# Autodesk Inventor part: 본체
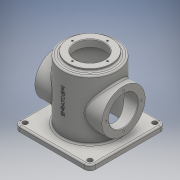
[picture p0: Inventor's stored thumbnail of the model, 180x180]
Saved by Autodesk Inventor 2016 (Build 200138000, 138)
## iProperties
Created: 2019-08
Part Number: 본체
Material: 일반
Document SubType Name: Modeling
Designer: user
Density: 1 g/cm^3
Appearance: 기본값
Author: user
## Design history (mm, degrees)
sketch "스케치1"
  geometry: L1 (-60, -70)-(60, -70); L2 (70, -60)-(70, 60); L3 (60, 70)-(-60, 70); L4 (-70, 60)-(-70, -60); L5 (-70, -70)-(70, 70); L6 (70, -70)-(-70, 70); A1 r 10 centre (-60, 60) between (-60, 70) and (-70, 60); A2 r 10 centre (60, 60) between (70, 60) and (60, 70); A3 r 10 centre (60, -60) between (60, -70) and (70, -60); A4 r 10 centre (-60, -60) between (-70, -60) and (-60, -70); 1 further point
  constraints: 12 end point, 8 point on circle, 8 point on line, 8 tangent, 4 centre point, 3 equal radius, 2 midpoint, 2 parallel, 1 horizontal, 1 perpendicular
  dimensions: "d0" = 140 distance of L5.end L6.end; "d1" = 140 distance of L6.start L5.end; "d2" = 10 radius of A1
extrude "돌출1" new body sketch "스케치1" distance "d3" = 10; taper "d4" = 0 deg
node "작업 평면1"
sketch "스케치8"
  geometry: C1 r 50 at (0, 0); 1 further point
  constraints: 1 centre point, 1 coincident
  dimensions: "d28" = 100 diameter of C1
extrude "돌출6" join sketch "스케치8" distance "d29" = 110; taper "d30" = 0 deg
node "작업 평면3"
sketch "스케치10"
  geometry: C1 r 40 at (0, 0); 1 further point
  constraints: 1 centre point, 1 coincident
  dimensions: "d32" = 80 diameter of C1
extrude "돌출7" join sketch "스케치10" stored distance "d33" = 110; taper "d34" = 0 deg
sketch "스케치11"
  geometry: L1 (-60, 70)-(60, 70) reference; L2 (70, 60)-(70, -60) reference; L3 (60, -70)-(-60, -70) reference; L4 (-70, -60)-(-70, 60) reference; C1 r 50 at (0, 0) reference; A1 r 10 centre (-60, 60) between (-60, 70) and (-70, 60) reference; A2 r 10 centre (60, 60) between (70, 60) and (60, 70) reference; A3 r 10 centre (60, -60) between (60, -70) and (70, -60) reference; A4 r 10 centre (-60, -60) between (-70, -60) and (-60, -70) reference; 5 further points
  constraints: 4 coincident
hole "구멍2" sketch "스케치11" at (-60, 60), (60, 60), (60, -60), (-60, -60) diameter "d35" = 9; stored, may be unused: countersink angle "d39" = 90 deg, drill point angle "d41" = 118 deg; dims "d36" = 6, "d37" = 4, "d38" = 2, "d40" = 8
node "작업 평면4"
sketch "스케치12"
  geometry: L1 (-60, 0)-(60, 0) reference; C1 r 40 at (0, 60); 2 further points
  constraints: 1 centre point, 1 midpoint, 1 vertical alignment
  dimensions: "d43" = 80 diameter of C1; "d44" = 60 distance from line of L1 C1.centre
extrude "돌출8" join sketch "스케치12" distance "d45" = 124; taper "d46" = 0 deg
sketch "스케치13"
  geometry: C1 r 45 at (0, 0); 1 further point
  constraints: 1 centre point, 1 coincident
  dimensions: "d47" = 90 diameter of C1
extrude "돌출9" cut sketch "스케치13" distance "d48" = 112; taper "d49" = 0 deg
sketch "스케치14"
  geometry: 2 further points
  constraints: 1 coincident
hole "구멍3" sketch "스케치14" at (0, 0) diameter "d50" = 54; stored, may be unused: countersink angle "d54" = 90 deg, drill point angle "d56" = 118 deg; dims "d51" = 6, "d52" = 4, "d53" = 2, "d55" = 8
sketch "스케치15"
  geometry: C1 r 40 at (0, 0) reference; 2 further points
  constraints: 1 coincident
hole "구멍4" sketch "스케치15" at (0, 0) diameter "d57" = 54; stored, may be unused: countersink angle "d61" = 90 deg, drill point angle "d63" = 118 deg; dims "d58" = 6, "d59" = 4, "d60" = 2, "d62" = 8
sketch "스케치16" dims "d64" = 65
  geometry: C1 r 27 at (0, 0) reference; 3 further points
  constraints: 2 vertical alignment, 1 coincident, 2 other
hole "구멍5" sketch "스케치16" at (0, -32.5) diameter "d65" = 3.242; stored, may be unused: countersink angle "d69" = 90 deg, drill point angle "d71" = 118 deg; dims "d66" = 8, "d67" = 4, "d68" = 2, "d70" = 10
sketch "스케치17" dims "d75" = 65
  geometry: 3 further points
  constraints: 2 vertical alignment, 1 coincident, 2 other
hole "구멍6" sketch "스케치17" at (0, 32.5) diameter "d76" = 3.242; stored, may be unused: countersink angle "d80" = 90 deg, drill point angle "d82" = 118 deg; dims "d77" = 8, "d78" = 4, "d79" = 2, "d81" = 10
chamfer "모따기1" distance "d86" = 1; stored, may be unused: second distance "d87" = 2, angle "d88" = 45 deg
fillet "모깎기1" dims "d89" = 3
fillet "모깎기2" dims "d90" = 3
fillet "모깎기3" dims "d91" = 3
fillet "모깎기4" dims "d92" = 3
fillet "모깎기5" dims "d93" = 3
chamfer "모따기2" distance "d94" = 1; stored, may be unused: second distance "d95" = 2, angle "d96" = 45 deg
node "작업 평면5"
sketch "스케치18" dims "d0" = 140, "d1" = 140, "d2" = 10
  geometry: L1 (-60, 0)-(60, 0) reference; 3 further points
  constraints: 1 midpoint, 1 vertical alignment, 1 other
  dimensions: "d98" = 70 distance from line of L1 point (0, 70)
feature "엠보싱1" sketch "스케치18" dims "d0" = 140, "d1" = 140, "d2" = 10, "d99" = 0.5, "d100" = 0
node "솔리드1"
pattern_circular "원형 패턴1" dims angle "d73" = 360 deg
mirror "대칭2"
pattern_circular "원형 패턴2" dims angle "d84" = 360 deg
node "투영된 루프1"
node "절단 모서리 투영2"
other parameters: "d31" = -125, "d42" = 62, "d97" = -71.25
